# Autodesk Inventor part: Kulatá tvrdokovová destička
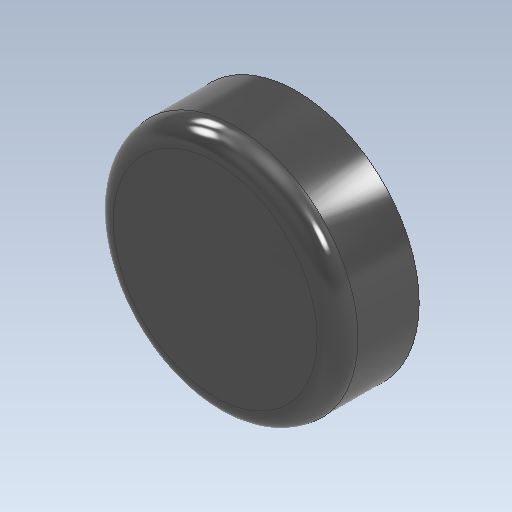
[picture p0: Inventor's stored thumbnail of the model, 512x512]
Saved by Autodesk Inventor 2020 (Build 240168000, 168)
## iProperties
Created: 2025-03
Part Number: Kulatá tvrdokovová destička
Material: Ocel
Document SubType Name: Modeling
Designer: doma
Density: 7.85 g/cm^3
Appearance: Tmavě šedá
Mass: 3.49011 g
Surface Area: 3.60366 cm^2
Volume: 0.4446 cm^3
Author: doma
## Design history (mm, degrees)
sketch "Náčrt1"
  geometry: C1 r 6 at (0, 0); 1 further point
  constraints: 1 centre point, 1 coincident
  dimensions: "d0" = 12 diameter of C1
extrude "Vysunutí1" new body sketch "Náčrt1" distance "d1" = 4; taper "d2" = 0 deg
fillet "Zaoblení1" dims "d3" = 1
node "Těleso1"
